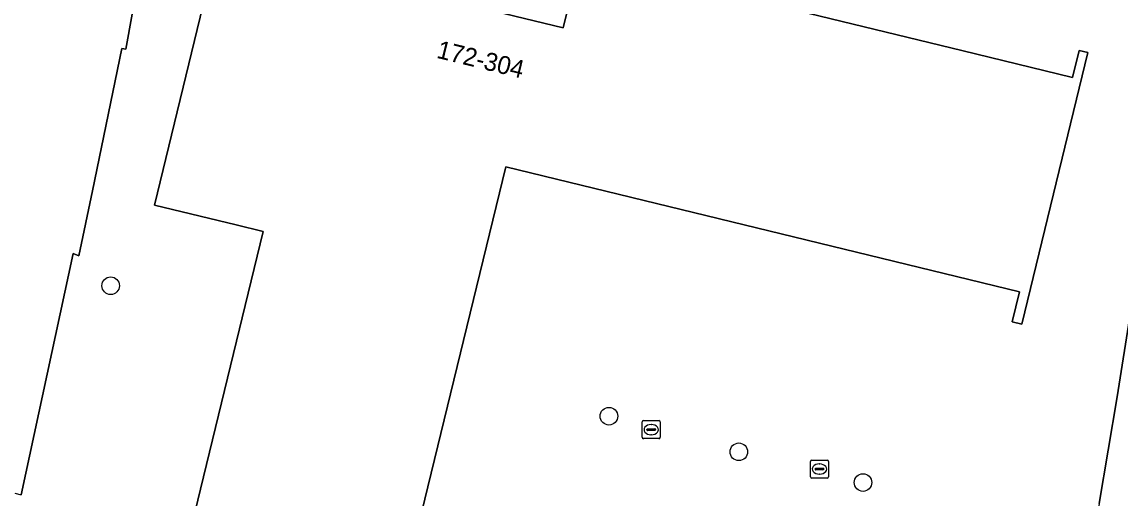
# Model space of a CAD drawing. Extents: x 162803 to 163818, y 381639 to 382475.
# Drawn here: x 163048.8 to 163109.9, y 382397.3 to 382423.7 of the extents above; entities that cross this region are included whole.
import ezdxf

# ---------------------------------------------------------------- set-up
doc = ezdxf.new("R2010")
doc.units = 0
for name, color, linetype in [('IMGEO_Boom', 7, 'Continuous'), ('IMGEO_Erf', 7, 'Continuous'), ('IMGEO_Kolk', 7, 'Continuous'), ('IMGEO_Pand', 7, 'Continuous'), ('IMGEO_Pand_nummerreeks', 7, 'Continuous'), ('IMGEO_Voetpad_open', 7, 'Continuous')]:
    doc.layers.add(name, color=color, linetype=linetype)

msp = doc.modelspace()

# ---------------------------------------------------------------- linework, layer by layer
at = {"layer": 'IMGEO_Boom'}
for centre in [(163053.752, 382409.068), (163081.445, 382401.82), (163088.663, 382399.844), (163095.565, 382398.135)]:
    msp.add_circle(centre, 0.489, dxfattribs=at)
at = {"layer": 'IMGEO_Erf'}
for points in [[(163108.694, 382396.964), (163109.688, 382402.897), (163112.543, 382420.938), (163112.75, 382422.426), (163113.395, 382426.511), (163102.776, 382429.01), (163081.558, 382434.002), (163076.134, 382435.357), (163059.186, 382439.194), (163058.429, 382438.955), (163057.549, 382434.766), (163057.269, 382434.813), (163056.547, 382430.876), (163056.692, 382430.848), (163056.668, 382430.717), (163055.342, 382426.312), (163054.592, 382422.204), (163054.372, 382422.252), (163052.737, 382414.344), (163051.991, 382410.736), (163051.66, 382410.862), (163048.783, 382397.461)], [(163052.803, 382373.333), (163062.233, 382412.073), (163060.72, 382412.442), (163056.185, 382413.546), (163059.045, 382425.293), (163060.173, 382429.928), (163060.422, 382430.951), (163074.154, 382427.608), (163073.45, 382424.716), (163078.908, 382423.387), (163080.205, 382428.713), (163080.693, 382428.594), (163080.347, 382427.171), (163101.063, 382422.129), (163107.213, 382420.632), (163107.581, 382422.143), (163108.064, 382422.025), (163104.397, 382406.934), (163103.858, 382407.056), (163104.264, 382408.73), (163075.707, 382415.682), (163064.719, 382370.542)]]:
    msp.add_lwpolyline(points, dxfattribs=at)
at = {"layer": 'IMGEO_Kolk'}
for p, q in [((163083.295, 382400.647), (163083.295, 382401.499)), ((163083.37, 382401.573), (163084.222, 382401.573)), ((163083.554, 382401.067), (163083.554, 382401.079)), ((163083.597, 382401.116), (163083.995, 382401.116)), ((163083.783, 382401.353), (163083.808, 382401.353)), ((163084.038, 382401.079), (163084.038, 382401.067)), ((163084.296, 382401.499), (163084.296, 382400.647)), ((163084.222, 382400.573), (163083.37, 382400.573)), ((163083.992, 382401.03), (163083.594, 382401.03)), ((163083.806, 382400.793), (163083.781, 382400.793)), ((163092.645, 382398.461), (163092.645, 382399.313)), ((163092.72, 382399.387), (163093.572, 382399.387)), ((163093.646, 382399.313), (163093.646, 382398.461)), ((163092.904, 382398.881), (163092.904, 382398.893)), ((163093.342, 382398.844), (163092.944, 382398.844)), ((163092.947, 382398.93), (163093.345, 382398.93)), ((163093.133, 382399.167), (163093.158, 382399.167)), ((163093.388, 382398.893), (163093.388, 382398.881)), ((163093.572, 382398.387), (163092.72, 382398.387)), ((163093.156, 382398.607), (163093.131, 382398.607))]:
    msp.add_line(p, q, dxfattribs=at)
for points in [[(163083.295, 382400.647), (163083.295, 382401.499)], [(163083.37, 382401.573), (163084.222, 382401.573)], [(163084.296, 382401.499), (163084.296, 382400.647)], [(163084.222, 382400.573), (163083.37, 382400.573)], [(163092.645, 382398.461), (163092.645, 382399.313)], [(163092.72, 382399.387), (163093.572, 382399.387)], [(163093.646, 382399.313), (163093.646, 382398.461)], [(163093.572, 382398.387), (163092.72, 382398.387)]]:
    msp.add_lwpolyline(points, dxfattribs=at)
for centre, radius, start, end in [((163083.372, 382401.497), 0.0765, 91.55205, 178.44795), ((163083.372, 382401.497), 0.0765, 91.55205, 178.44795), ((163083.594, 382401.076), 0.0403, 85.87752, 175.75265), ((163083.999, 382401.078), 0.0386, 1.73085, 96.63898), ((163084.22, 382401.497), 0.0765, 1.55205, 88.44795), ((163084.22, 382401.497), 0.0765, 1.55205, 88.44795), ((163083.372, 382400.649), 0.0765, 181.55205, 268.44795), ((163083.372, 382400.649), 0.0765, 181.55205, 268.44795), ((163083.591, 382401.066), 0.0366, 178.93798, 274.71019), ((163083.995, 382401.073), 0.043, 264.86636, 352.45326), ((163084.22, 382400.649), 0.0765, 271.55205, 358.44795), ((163084.22, 382400.649), 0.0765, 271.55205, 358.44795), ((163092.722, 382399.311), 0.0765, 91.55205, 178.44795), ((163092.722, 382399.311), 0.0765, 91.55205, 178.44795), ((163093.57, 382399.311), 0.0765, 1.55205, 88.44795), ((163093.57, 382399.311), 0.0765, 1.55205, 88.44795), ((163092.944, 382398.89), 0.0403, 85.87752, 175.75265), ((163092.941, 382398.88), 0.0366, 178.93798, 274.71019), ((163093.345, 382398.887), 0.043, 264.86636, 352.45326), ((163093.349, 382398.892), 0.0386, 1.73085, 96.63898), ((163092.722, 382398.463), 0.0765, 181.55205, 268.44795), ((163092.722, 382398.463), 0.0765, 181.55205, 268.44795), ((163093.57, 382398.463), 0.0765, 271.55205, 358.44795), ((163093.57, 382398.463), 0.0765, 271.55205, 358.44795)]:
    msp.add_arc(centre, radius, start, end, dxfattribs=at)
for centre, major_axis, ratio, start_param, end_param in [((163083.782, 382401.073), (-0.387, 0.002), 0.722429, 4.712389, 7.853982), ((163083.807, 382401.073), (-0.39, 0.002), 0.717154, 1.570796, 4.712389), ((163093.132, 382398.887), (-0.387, 0.002), 0.722429, 4.712389, 7.853982), ((163093.157, 382398.887), (-0.39, 0.002), 0.717154, 1.570796, 4.712389)]:
    msp.add_ellipse(centre, major_axis=major_axis, ratio=ratio, start_param=start_param, end_param=end_param, dxfattribs=at)
at = {"layer": 'IMGEO_Pand'}
msp.add_lwpolyline([(163064.719, 382370.542), (163075.707, 382415.682), (163104.264, 382408.73), (163103.858, 382407.056), (163104.397, 382406.934), (163108.064, 382422.025), (163107.581, 382422.143), (163107.213, 382420.632), (163101.063, 382422.129), (163080.347, 382427.171), (163080.693, 382428.594), (163080.205, 382428.713), (163078.908, 382423.387), (163073.45, 382424.716), (163074.154, 382427.608), (163060.422, 382430.951), (163060.173, 382429.928), (163059.045, 382425.293), (163056.185, 382413.546), (163060.72, 382412.442), (163062.233, 382412.073), (163052.803, 382373.333)], dxfattribs=at)
at = {"layer": 'IMGEO_Voetpad_open'}
for points in [[(163048.422, 382397.537), (163048.783, 382397.461), (163051.66, 382410.862), (163051.991, 382410.736), (163052.737, 382414.344), (163054.372, 382422.252), (163054.592, 382422.204), (163055.342, 382426.312), (163056.668, 382430.717), (163056.692, 382430.848), (163056.547, 382430.876), (163057.269, 382434.813), (163057.549, 382434.766), (163058.429, 382438.955), (163058.976, 382443.327)], [(163116.24, 382425.96), (163113.395, 382426.511), (163112.75, 382422.426), (163112.543, 382420.938), (163109.688, 382402.897), (163108.694, 382396.964), (163103.117, 382362.845)]]:
    msp.add_lwpolyline(points, dxfattribs=at)

# ---------------------------------------------------------------- texts
at = {"layer": 'IMGEO_Pand_nummerreeks'}
msp.add_text('172-304', height=1, rotation=346.31503, dxfattribs=at).set_placement((163071.819, 382421.737))

doc.saveas('drawing.dxf')
